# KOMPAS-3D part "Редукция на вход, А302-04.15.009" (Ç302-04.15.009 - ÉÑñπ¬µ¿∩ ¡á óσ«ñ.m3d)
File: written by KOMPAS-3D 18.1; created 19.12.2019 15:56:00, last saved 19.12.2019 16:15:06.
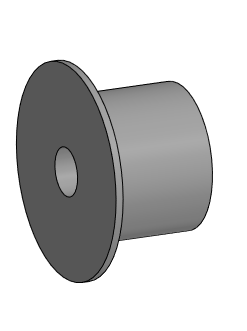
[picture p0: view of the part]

Document properties: Полное имя файла: D:\Мембранные насосы\Мембранный электропривод\А302-00.00.000 - ASTRA-302 (МЭ200)\А302-04.00.000 - Мембранный насос ASTRA-302-PP\А302-04.15.009 - Редукция на вход.m3d

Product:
- Part/product: Редукция на вход  | designation А302-04.15.009
    Материал: Полипропилен  ГОСТ 26996-86 (density 900 kg/m3)
    Масса: 0.0322027

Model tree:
1. Эскиз:1
2. Элемент вращения:1  (labels: Полипропилен  ГОСТ 26996-86)
     Угол 1 = 360

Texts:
  Линейный размер с обрывом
